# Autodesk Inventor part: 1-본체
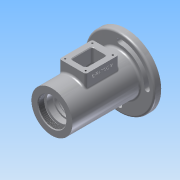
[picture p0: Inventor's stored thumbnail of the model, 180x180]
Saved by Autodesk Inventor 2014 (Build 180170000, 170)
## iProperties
Created: 2017-05
Part Number: 1-본체
Material: Aluminum 6061
Document SubType Name: Modeling
Designer: user
Density: 2.71 g/cm^3
Appearance: Aluminum - Flat
Mass: 679.728 g
Surface Area: 615.711 cm^2
Volume: 250.822 cm^3
Author: user
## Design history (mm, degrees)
sketch "Sketch1"
  geometry: L1 (0, 0)-(115, 0); L2 (0, 0)-(0, 31); L3 (0, 31)-(102, 31); L4 (102, 31)-(102, 53); L5 (102, 53)-(112, 53); L6 (112, 53)-(112, 31); L7 (112, 31)-(115, 31); L8 (115, 31)-(115, 0)
  constraints: 16 end point, 4 parallel, 2 perpendicular, 1 collinear, 1 horizontal
  dimensions: "d0" = 62 diameter of L3 L1; "d1" = 106 diameter of L5 L1; "d2" = 62 diameter of L7 L1; "d3" = 10 distance of L4.end L5.end; "d4" = 3 distance from line of L5.end L8; "d5" = 115 distance between parallel lines of L2 L8
revolve "Revolution1" sketch "Sketch1" stored, may be unused: angle "d6" = 90 deg
sketch "Sketch4"
  geometry: L1 (0, 0)-(115, 0); L2 (115, -31)-(115, 31) reference; L3 (0, 0)-(0, 21); L4 (0, 21)-(9, 21); L5 (0, -31)-(0, 31) reference; L6 (9, 21)-(9, 24); L7 (0, 31)-(102, 31) reference; L8 (9, 24)-(12, 24); L9 (12, 24)-(12, 20); L10 (12, 20)-(21, 20); L11 (21, 20)-(21, 17.5); L12 (21, 17.5)-(24.25, 17.5); L13 (24.25, 17.5)-(24.25, 18.5); L14 (24.25, 18.5)-(26, 18.5); L15 (26, 18.5)-(26, 17.5); L16 (26, 17.5)-(37, 17.5); L17 (37, 17.5)-(37, 26); L18 (37, 26)-(75, 26); L19 (75, 26)-(75, 17.5); L20 (75, 17.5)-(86, 17.5); L21 (86, 17.5)-(86, 16.5); L22 (86, 16.5)-(91, 16.5); L23 (91, 16.5)-(91, 10); L24 (91, 10)-(93.7, 10); L25 (93.7, 10)-(93.7, 12.5); L26 (93.7, 12.5)-(101, 12.5); L27 (101, 12.5)-(101, 16); L28 (101, 16)-(115, 22); L29 (115, 0)-(115, 22)
  constraints: 52 end point, 12 parallel, 11 perpendicular, 1 collinear, 1 midpoint, 1 point on line, 1 vertical
  dimensions: "d10" = 42 diameter of L4 L1; "d11" = 48 diameter of L8 L1; "d12" = 40 diameter of L10 L1; "d13" = 3 distance of L6.end L8.end; "d14" = 12 distance between parallel lines of L9 L5; "d15" = 21 distance between parallel lines of L5 L11; "d16" = 1.75 distance of L13.end L14.end; "d17" = 37 diameter of L14 L1; "d18" = 35 diameter of L12 L1; "d19" = 26 distance from line of L5 L14.end; "d20" = 11 distance of L15.end L16.end; "d21" = 35 diameter of L16 L1; "d22" = 52 diameter of L18 L1; "d29" = 38 distance of L17.end L18.end; "d33" = 35 diameter of L20 L1; "d34" = 11 distance of L19.end L20.end; "d35" = 32 diameter of L27.end L1; "d36" = 44 diameter of L28.end L1; "d37" = 14 distance from line of L2 L27.end; "d38" = 25 diameter of L26 L1; "d39" = 20 diameter of L24 L1; "d40" = 7.3 distance between parallel lines of L25 L27; "d41" = 2.7 distance of L23.end L24.end; "d42" = 33 diameter of L22 L1
revolve "Revolution2" sketch "Sketch4" stored, may be unused: angle "d43" = 90 deg
workplane "Work Plane2"
sketch "Sketch5"
  geometry: L1 (-81, 20)-(-31, 20); L2 (-31, 20)-(-31, -20); L3 (-31, -20)-(-81, -20); L4 (-81, -20)-(-81, 20); L5 (0, 31)-(0, -31) reference; 1 further point
  constraints: 8 end point, 2 parallel, 1 horizontal, 1 perpendicular
  dimensions: "d46" = 50 distance of L1.start L1.end; "d47" = 20 vertical distance of point (0, 0) L1.end; "d48" = 40 distance of L1.end L2.end; "d49" = 31 distance between parallel lines of L5 L2
extrude "Extrusion1" join sketch "Sketch5" stored distance "d50" = 10; taper "d51" = 0 deg
sketch "Sketch6"
  geometry: L1 (-72, 11)-(-40, 11); L2 (-40, 11)-(-40, -11); L3 (-40, -11)-(-72, -11); L4 (-72, -11)-(-72, 11); L5 (0, 31)-(0, -31) reference; 1 further point
  constraints: 8 end point, 2 parallel, 1 horizontal, 1 perpendicular
  dimensions: "d52" = 22 distance of L1.end L2.end; "d53" = 11 distance from line of point (0, 0) L1; "d54" = 32 distance of L1.start L1.end; "d55" = 40 distance between parallel lines of L5 L2
extrude "Extrusion2" cut sketch "Sketch6" stored distance "d56" = 10; taper "d57" = 0 deg
sketch "Sketch7"
  geometry: L1 (0, 31)-(0, -31) reference; 2 further points
  dimensions: "d58" = 15.5 vertical distance of point (0, 0) point (-35.5, 15.5); "d59" = 35.5 distance from line of L1 point (-35.5, 15.5)
hole "Hole1" sketch "Sketch7" at (-35.5, 15.5) diameter "d60" = 2.459; stored, may be unused: countersink angle "d64" = 90 deg, drill point angle "d66" = 118 deg; dims "d61" = 6, "d62" = 4, "d63" = 2, "d65" = 8
pattern_linear "Rectangular Pattern1" dims "d69" = 31, "d72" = 41
sketch "Sketch8"
  geometry: L1 (0, 0)-(45.5, 0); L2 (44, 20)-(44, -20) reference; L3 (0, 0)-(0, 45.5); L4 (0, 0)-(-45.5, 0); L5 (0, 0)-(0, -45.5); C1 r 31 at (0, 0) reference; C2 r 10 at (0, 0) reference; A1 r 4 centre (0, 41.5) between (0, 45.5) and (0, 37.5); A2 r 4 centre (41.5, 0) between (37.5, 0) and (45.5, 0); A3 r 4 centre (0, -41.5) between (0, -45.5) and (0, -37.5); A4 r 4 centre (-41.5, 0) between (-37.5, 0) and (-45.5, 0); A5 r 37.5 centre (0, 0) between (37.5, 0) and (0, 37.5); A6 r 37.5 centre (0, 0) between (-37.5, 0) and (0, -37.5); A7 r 45.5 centre (0, 0) between (45.5, 0) and (0, 45.5); A8 r 45.5 centre (0, 0) between (-45.5, 0) and (0, -45.5)
  constraints: 16 point on circle, 8 centre point, 8 end point, 4 point on line, 3 perpendicular, 2 coincident, 2 concentric, 1 parallel
  dimensions: "d75" = 4 radius of A1; "d76" = 4 radius of A2; "d77" = 4 radius of A3; "d78" = 4 radius of A4; "d81" = 45.5 radius of A7; "d82" = 37.5 radius of A5
extrude "Extrusion3" cut sketch "Sketch8" distance "d79" = 20; taper "d80" = 0 deg
thread "Thread1" dims "d83" = 10, "d84" = 0
sketch "Sketch9"
  geometry: L1 (0, 0)-(50, 0) reference; L2 (81, 75)-(81, 13) reference; 2 further points
  constraints: 1 other
  dimensions: "d85" = 56 distance from line of L2 point (25, 8); "d86" = 8 distance from line of L1 point (25, 8)
emboss "Emboss1" sketch "Sketch9" dims "d0" = 62, "d1" = 106, "d2" = 62, "d3" = 10, "d4" = 3, "d5" = 115, "d87" = 0.5, "d88" = 0
chamfer "Chamfer1" distance "d89" = 1; stored, may be unused: second distance "d90" = 2, angle "d91" = 45 deg
chamfer "Chamfer2" distance "d92" = 0.7; stored, may be unused: second distance "d93" = 2, angle "d94" = 30 deg
fillet "Fillet1" dims "d95" = 3, "d96" = 0.3
chamfer "Chamfer3" distance "d97" = 1; stored, may be unused: second distance "d98" = 2, angle "d99" = 30 deg
fillet "Fillet2" dims "d100" = 3, "d101" = 0.3
body "Solid1"
other parameters: "d44" = 44, "d73" = 91, "d74" = 75
